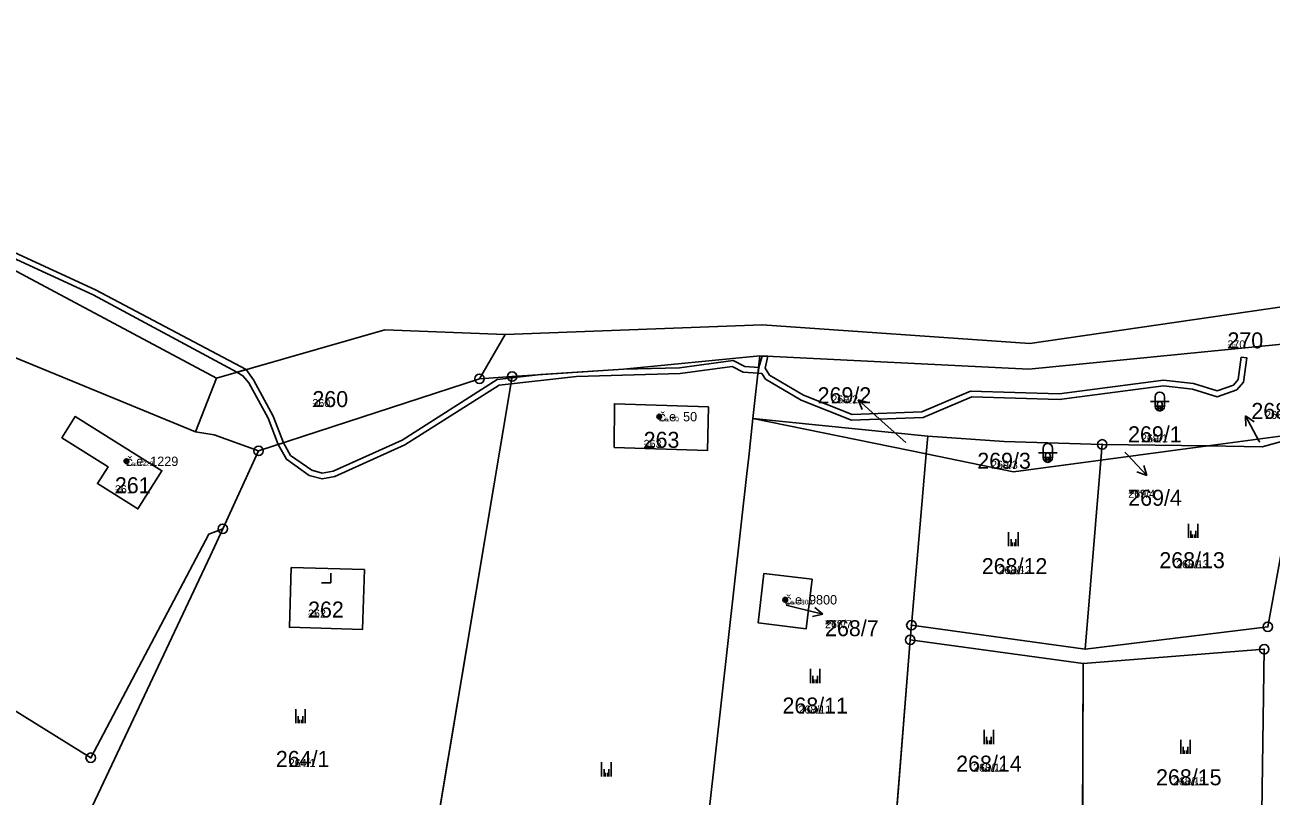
# Model space of a CAD drawing. Extents: x -759873 to -758487, y -975024 to -973516.
# Drawn here: x -758821 to -758688.7, y -974723.5 to -974641.6 of the extents above; entities that cross this region are included whole.
import ezdxf

# ---------------------------------------------------------------- set-up
doc = ezdxf.new("R2010")
doc.units = 0
for name, color, linetype in [('KAT_02_hranice parcel', 7, 'Continuous'), ('KAT_03_1000_st čísla parcelní', 7, 'Continuous'), ('KAT_03_1000_čísla parcelní', 7, 'Continuous'), ('KAT_03_1000_čísla popisná', 7, 'Continuous'), ('KAT_03_250_st čísla parcelní', 7, 'Continuous'), ('KAT_03_250_čísla parcelní', 7, 'Continuous'), ('KAT_03_250_čísla popisná', 7, 'Continuous'), ('KAT_03_500_st čísla parcelní', 7, 'Continuous'), ('KAT_03_500_čísla parcelní', 7, 'Continuous'), ('KAT_03_500_čísla popisná', 7, 'Continuous'), ('KAT_05_1000_značky kultur', 7, 'Continuous'), ('KAT_05_250_značky kultur', 7, 'Continuous'), ('KAT_05_500_značky kultur', 7, 'Continuous'), ('KAT_07_1000_značky budov', 7, 'Continuous'), ('KAT_07_250_značky budov', 7, 'Continuous'), ('KAT_07_500_značky budov', 7, 'Continuous'), ('KAT_10_věcná břemena', 7, 'Continuous'), ('KAT_11_značky bodu BP', 7, 'Continuous'), ('KAT_12_pomocná šipka', 7, 'Continuous'), ('KAT_14_plocha_budovy', 7, 'Continuous'), ('KAT_14_plocha_pozemek', 7, 'Continuous')]:
    doc.layers.add(name, color=color, linetype=linetype)

msp = doc.modelspace()

# ---------------------------------------------------------------- linework, layer by layer
at = {"layer": 'KAT_02_hranice parcel'}
for p, q in [((-758772.79, -974679.2), (-758770.04, -974674.49)), ((-758743, -974676.78), (-758743.77, -974683.44)), ((-758802.92, -974684.85), (-758800.69, -974679.14)), ((-758796.23, -974686.87), (-758772.79, -974679.2)), ((-758780.91, -974748.2), (-758769.32, -974678.97)), ((-758772.79, -974679.2), (-758769.32, -974678.97)), ((-758743.77, -974683.44), (-758725.19, -974685.31)), ((-758743.77, -974683.44), (-758725.35, -974687.19)), ((-758695.47, -974686.34), (-758686.97, -974685.21)), ((-758725.35, -974687.19), (-758725.19, -974685.31)), ((-758706.8, -974687.84), (-758706.66, -974686.17)), ((-758706.8, -974687.84), (-758695.47, -974686.34)), ((-758706.66, -974686.17), (-758695.47, -974686.34)), ((-758800.04, -974695.13), (-758796.23, -974686.87)), ((-758726.93, -974705.38), (-758725.35, -974687.19)), ((-758708.48, -974707.93), (-758706.8, -974687.84)), ((-758726.93, -974705.38), (-758727.05, -974706.93)), ((-758708.48, -974707.93), (-758726.93, -974705.38)), ((-758728.61, -974726.68), (-758727.05, -974706.93)), ((-758727.05, -974706.93), (-758708.68, -974709.44)), ((-758708.76, -974729.74), (-758708.68, -974709.44))]:
    msp.add_line(p, q, dxfattribs=at)
for points in [[(-758800.69, -974679.14), (-758829.75, -974663.64), (-758830.87, -974663.12)], [(-758627.78, -974672.1), (-758635.66, -974671.11), (-758664.13, -974667.52), (-758681.5, -974670.69), (-758714.34, -974675.47), (-758742.76, -974673.48), (-758770.04, -974674.49)], [(-758846.61, -974699.26), (-758838.64, -974683.01), (-758833.34, -974672.35), (-758802.92, -974684.85)], [(-758770.04, -974674.49), (-758782.83, -974674), (-758800.69, -974679.14)], [(-758743, -974676.78), (-758714.44, -974678.18), (-758679.66, -974674.74)], [(-758769.32, -974678.97), (-758757.5, -974678.19), (-758743, -974676.78)], [(-758748.48, -974682.19), (-758758.46, -974681.86), (-758758.48, -974686.49), (-758748.56, -974686.81), (-758748.48, -974682.19)], [(-758815.7, -974683.2), (-758806.5, -974688.97), (-758809.05, -974693.03), (-758813.35, -974690.34), (-758812.22, -974688.54), (-758817.12, -974685.46), (-758815.7, -974683.2)], [(-758743.77, -974683.44), (-758744.2, -974687.51), (-758744.4, -974689.28), (-758748.41, -974725.03)], [(-758796.23, -974686.87), (-758800.96, -974685.16), (-758802.92, -974684.85)], [(-758725.19, -974685.31), (-758717.09, -974685.85), (-758706.66, -974686.17)], [(-758695.47, -974686.34), (-758689.7, -974686.42), (-758687.25, -974685.75)], [(-758725.35, -974687.19), (-758716.08, -974689.07), (-758706.8, -974687.84)], [(-758686.52, -974691.5), (-758689.09, -974705.54), (-758708.48, -974707.93)], [(-758846.61, -974699.26), (-758814.06, -974719.44), (-758801.52, -974695.69), (-758800.04, -974695.13)], [(-758820.96, -974734.87), (-758818.51, -974734.4), (-758801.37, -974698.03), (-758800.04, -974695.13)], [(-758792.77, -974699.23), (-758792.96, -974705.59), (-758785.19, -974705.82), (-758785, -974699.46), (-758792.77, -974699.23)], [(-758742.58, -974699.88), (-758743.21, -974705.11), (-758738.1, -974705.76), (-758737.47, -974700.5), (-758742.58, -974699.88)], [(-758708.68, -974709.44), (-758689.46, -974707.93), (-758689.78, -974730.19)]]:
    msp.add_lwpolyline(points, dxfattribs=at)
at = {"layer": 'KAT_03_1000_čísla popisná'}
for centre in [(-758753.69, -974683.23), (-758810.26, -974687.97), (-758740.32, -974702.67)]:
    msp.add_circle(centre, 0.25, dxfattribs=at)
at = {"layer": 'KAT_03_250_čísla popisná'}
for centre in [(-758753.69, -974683.23), (-758810.26, -974687.97), (-758740.32, -974702.67)]:
    msp.add_circle(centre, 0.0625, dxfattribs=at)
at = {"layer": 'KAT_03_500_čísla popisná'}
for centre in [(-758753.69, -974683.23), (-758810.26, -974687.97), (-758740.32, -974702.67)]:
    msp.add_circle(centre, 0.125, dxfattribs=at)
at = {"layer": 'KAT_05_1000_značky kultur'}
for p, q in [((-758701.05, -974681.12), (-758701.05, -974682.12)), ((-758700.05, -974682.12), (-758700.05, -974681.12)), ((-758701.55, -974681.62), (-758699.55, -974681.62)), ((-758713.44, -974687.08), (-758711.44, -974687.08)), ((-758712.94, -974686.58), (-758712.94, -974687.58)), ((-758711.94, -974687.58), (-758711.94, -974686.58)), ((-758716.6, -974696.98), (-758716.6, -974695.48)), ((-758715.6, -974696.98), (-758715.6, -974695.48)), ((-758697.5, -974696.11), (-758697.5, -974694.61)), ((-758696.5, -974696.11), (-758696.5, -974694.61)), ((-758789.57, -974700.86), (-758788.57, -974700.86)), ((-758788.57, -974700.86), (-758788.57, -974699.86)), ((-758737.65, -974711.51), (-758737.65, -974710.01)), ((-758736.65, -974711.51), (-758736.65, -974710.01)), ((-758792.29, -974715.79), (-758792.29, -974714.29)), ((-758791.29, -974715.79), (-758791.29, -974714.29)), ((-758719.21, -974717.99), (-758719.21, -974716.49)), ((-758718.21, -974717.99), (-758718.21, -974716.49)), ((-758698.33, -974719.03), (-758698.33, -974717.53)), ((-758697.33, -974719.03), (-758697.33, -974717.53)), ((-758759.81, -974721.42), (-758759.81, -974719.92)), ((-758758.81, -974721.42), (-758758.81, -974719.92))]:
    msp.add_line(p, q, dxfattribs=at)
for centre, start, end in [((-758700.55, -974681.12), 0, 180), ((-758700.55, -974682.12), 180, 359.9879), ((-758712.44, -974686.58), 0, 180), ((-758712.44, -974687.58), 180, 359.9879)]:
    msp.add_arc(centre, 0.5, start, end, dxfattribs=at)
at = {"layer": 'KAT_05_250_značky kultur'}
for p, q in [((-758700.8, -974682.37), (-758700.3, -974682.37)), ((-758700.68, -974682.25), (-758700.68, -974682.5)), ((-758700.42, -974682.5), (-758700.42, -974682.25)), ((-758712.69, -974687.83), (-758712.19, -974687.83)), ((-758712.57, -974687.71), (-758712.57, -974687.96)), ((-758712.31, -974687.96), (-758712.31, -974687.71)), ((-758697.12, -974696.11), (-758697.12, -974695.73)), ((-758696.87, -974696.11), (-758696.87, -974695.73)), ((-758716.22, -974696.98), (-758716.22, -974696.6)), ((-758715.97, -974696.98), (-758715.97, -974696.6)), ((-758788.82, -974700.86), (-758788.57, -974700.86)), ((-758788.57, -974700.86), (-758788.57, -974700.61)), ((-758737.27, -974711.51), (-758737.27, -974711.14)), ((-758737.02, -974711.51), (-758737.02, -974711.14)), ((-758791.91, -974715.79), (-758791.91, -974715.42)), ((-758791.66, -974715.79), (-758791.66, -974715.42)), ((-758718.83, -974717.99), (-758718.83, -974717.61)), ((-758718.58, -974717.99), (-758718.58, -974717.61)), ((-758697.95, -974719.03), (-758697.95, -974718.66)), ((-758697.7, -974719.03), (-758697.7, -974718.66)), ((-758759.43, -974721.42), (-758759.43, -974721.05)), ((-758759.18, -974721.42), (-758759.18, -974721.05))]:
    msp.add_line(p, q, dxfattribs=at)
for centre, start, end in [((-758700.55, -974682.25), 0, 180), ((-758700.55, -974682.5), 180, 359.9879), ((-758712.44, -974687.71), 0, 180), ((-758712.44, -974687.96), 180, 359.9879)]:
    msp.add_arc(centre, 0.125, start, end, dxfattribs=at)
at = {"layer": 'KAT_05_500_značky kultur'}
for p, q in [((-758701.05, -974682.12), (-758700.05, -974682.12)), ((-758700.8, -974681.87), (-758700.8, -974682.37)), ((-758700.3, -974682.37), (-758700.3, -974681.87)), ((-758712.94, -974687.58), (-758711.94, -974687.58)), ((-758712.69, -974687.33), (-758712.69, -974687.83)), ((-758712.19, -974687.83), (-758712.19, -974687.33)), ((-758697.25, -974696.11), (-758697.25, -974695.36)), ((-758696.74, -974696.11), (-758696.74, -974695.36)), ((-758716.35, -974696.98), (-758716.35, -974696.23)), ((-758715.84, -974696.98), (-758715.84, -974696.23)), ((-758789.07, -974700.86), (-758788.57, -974700.86)), ((-758788.57, -974700.86), (-758788.57, -974700.36)), ((-758737.4, -974711.51), (-758737.4, -974710.76)), ((-758736.9, -974711.51), (-758736.9, -974710.76)), ((-758792.04, -974715.79), (-758792.04, -974715.04)), ((-758791.54, -974715.79), (-758791.54, -974715.04)), ((-758718.96, -974717.99), (-758718.96, -974717.24)), ((-758718.45, -974717.99), (-758718.45, -974717.24)), ((-758698.08, -974719.03), (-758698.08, -974718.28)), ((-758697.58, -974719.03), (-758697.58, -974718.28)), ((-758759.56, -974721.42), (-758759.56, -974720.67)), ((-758759.06, -974721.42), (-758759.06, -974720.67))]:
    msp.add_line(p, q, dxfattribs=at)
for centre, start, end in [((-758700.55, -974681.87), 0, 180), ((-758700.55, -974682.37), 180, 359.9879), ((-758712.44, -974687.33), 0, 180), ((-758712.44, -974687.83), 180, 359.9879)]:
    msp.add_arc(centre, 0.25, start, end, dxfattribs=at)
at = {"layer": 'KAT_07_1000_značky budov'}
for centre in [(-758753.7, -974683.23), (-758810.27, -974687.97), (-758740.33, -974702.67)]:
    msp.add_circle(centre, 0.175, dxfattribs=at)
at = {"layer": 'KAT_07_250_značky budov'}
for centre in [(-758753.69, -974683.23), (-758810.26, -974687.97), (-758740.32, -974702.67)]:
    msp.add_circle(centre, 0.0437, dxfattribs=at)
at = {"layer": 'KAT_07_500_značky budov'}
for centre in [(-758753.69, -974683.23), (-758810.26, -974687.97), (-758740.32, -974702.67)]:
    msp.add_circle(centre, 0.0875, dxfattribs=at)
at = {"layer": 'KAT_10_věcná břemena'}
for points in [[(-758863.87, -974647.67), (-758863.33, -974647.93), (-758851.2, -974653.17), (-758831.96, -974661.95), (-758813.8, -974670.31), (-758798.54, -974678.52), (-758797.54, -974678.23), (-758813.54, -974669.77), (-758831.72, -974661.41), (-758850.96, -974652.63), (-758863.11, -974647.4), (-758862.12, -974644.3), (-758862.83, -974644.55), (-758863.76, -974647.45)], [(-758794.17, -974686.19), (-758793.27, -974687.76), (-758790.85, -974689.47), (-758789.5, -974689.84), (-758788.13, -974689.59), (-758780.71, -974686.23), (-758770.7, -974679.87), (-758762.49, -974678.95), (-758751.49, -974678.63), (-758745.95, -974677.89), (-758744.8, -974678.5), (-758743.21, -974678.62), (-758743.14, -974678.02), (-758744.62, -974677.92), (-758745.83, -974677.27), (-758751.53, -974678.03), (-758757.5, -974678.19), (-758766.26, -974678.77), (-758770.9, -974679.29), (-758780.99, -974685.71), (-758788.31, -974689.01), (-758789.48, -974689.22), (-758790.59, -974688.91), (-758792.83, -974687.34), (-758793.6, -974686.01)], [(-758743.14, -974678.02), (-758743.21, -974678.62), (-758742.8, -974678.65), (-758742.4, -974679.25), (-758738.64, -974681.47), (-758733.3, -974683.59), (-758725.68, -974683.33), (-758720.52, -974681.11), (-758711.23, -974681.42), (-758700.16, -974679.97), (-758697.09, -974680.31), (-758694.45, -974681.14), (-758692.38, -974680.37), (-758691.68, -974679.56), (-758691.31, -974676.99), (-758691.9, -974676.9), (-758692.24, -974679.3), (-758692.74, -974679.87), (-758694.47, -974680.5), (-758696.97, -974679.71), (-758700.16, -974679.37), (-758711.25, -974680.82), (-758720.64, -974680.51), (-758725.82, -974682.73), (-758733.2, -974682.99), (-758738.38, -974680.93), (-758741.98, -974678.81), (-758742.45, -974678.09), (-758742.18, -974676.82), (-758742.78, -974676.79)], [(-758797.54, -974678.23), (-758798.54, -974678.52), (-758797.89, -974678.88), (-758797.27, -974679.65), (-758795.21, -974683.4), (-758794.17, -974686.19), (-758793.6, -974686.01), (-758794.67, -974683.16), (-758796.77, -974679.31)]]:
    msp.add_lwpolyline(points, close=True, dxfattribs=at)
at = {"layer": 'KAT_11_značky bodu BP'}
for centre, radius in [((-758769.32, -974678.97), 0.5), ((-758772.79, -974679.2), 0.5), ((-758772.79, -974679.2), 0.0303), ((-758769.32, -974678.97), 0.0303), ((-758796.23, -974686.87), 0.5), ((-758706.66, -974686.17), 0.5), ((-758706.66, -974686.17), 0.0303), ((-758796.23, -974686.87), 0.0303), ((-758800.04, -974695.13), 0.5), ((-758800.04, -974695.13), 0.0303), ((-758726.93, -974705.38), 0.5), ((-758689.09, -974705.54), 0.5), ((-758726.93, -974705.38), 0.0303), ((-758689.09, -974705.54), 0.0303), ((-758727.05, -974706.93), 0.5), ((-758727.05, -974706.93), 0.0303), ((-758689.46, -974707.93), 0.5), ((-758689.46, -974707.93), 0.0303), ((-758814.06, -974719.44), 0.5), ((-758814.06, -974719.44), 0.0303)]:
    msp.add_circle(centre, radius, dxfattribs=at)
at = {"layer": 'KAT_12_pomocná šipka'}
for p, q in [((-758730.34, -974683.45), (-758732.57, -974681.44)), ((-758732.57, -974681.44), (-758731.49, -974681.74)), ((-758732.57, -974681.44), (-758732.16, -974682.48)), ((-758727.51, -974685.96), (-758730.34, -974683.45)), ((-758690.03, -974685.78), (-758691.44, -974683.13)), ((-758691.44, -974683.13), (-758690.53, -974683.78)), ((-758691.44, -974683.13), (-758691.41, -974684.25)), ((-758689.94, -974685.95), (-758690.03, -974685.78)), ((-758704.26, -974687), (-758703.99, -974687.28)), ((-758703.99, -974687.28), (-758701.94, -974689.47)), ((-758701.94, -974689.47), (-758702.99, -974689.08)), ((-758701.94, -974689.47), (-758702.26, -974688.4)), ((-758740.21, -974703.24), (-758739.23, -974703.48)), ((-758739.23, -974703.48), (-758736.32, -974704.21)), ((-758736.32, -974704.21), (-758737.17, -974703.48)), ((-758736.32, -974704.21), (-758737.41, -974704.45))]:
    msp.add_line(p, q, dxfattribs=at)
at = {"layer": 'KAT_14_plocha_budovy'}
for points in [[(-758758.48, -974686.49), (-758748.56, -974686.81), (-758748.48, -974682.19), (-758758.46, -974681.86)], [(-758817.12, -974685.46), (-758812.22, -974688.54), (-758813.35, -974690.34), (-758809.05, -974693.03), (-758806.5, -974688.97), (-758815.7, -974683.2)], [(-758743.21, -974705.11), (-758738.1, -974705.76), (-758737.47, -974700.5), (-758742.58, -974699.88)]]:
    msp.add_lwpolyline(points, close=True, dxfattribs=at)
at = {"layer": 'KAT_14_plocha_pozemek'}
for points in [[(-758829.75, -974663.64), (-758800.69, -974679.14), (-758782.83, -974674), (-758770.04, -974674.49), (-758742.76, -974673.48), (-758714.34, -974675.47), (-758681.5, -974670.69), (-758664.13, -974667.52), (-758635.66, -974671.11), (-758627.78, -974672.1), (-758618.81, -974624.26), (-758621.91, -974623.53), (-758624.96, -974622.82), (-758670.31, -974612.18), (-758699.89, -974599.55), (-758726.38, -974585.65), (-758760.58, -974546.71), (-758797.73, -974511.01)], [(-758686.52, -974691.5), (-758689.09, -974705.54), (-758708.48, -974707.93), (-758726.93, -974705.38), (-758727.05, -974706.93), (-758708.68, -974709.44), (-758689.46, -974707.93), (-758689.78, -974730.19)]]:
    msp.add_lwpolyline(points, dxfattribs=at)
for points in [[(-758830.87, -974663.12), (-758834.94, -974670.75), (-758841.44, -974684.62), (-758853.59, -974681.81), (-758863.06, -974680.54), (-758877.35, -974674.93), (-758892.08, -974697.79), (-758892.74, -974704.7), (-758858.23, -974722.43), (-758855, -974716.35), (-758846.61, -974699.26), (-758838.64, -974683.01), (-758833.34, -974672.35), (-758802.92, -974684.85), (-758800.69, -974679.14), (-758829.75, -974663.64)], [(-758757.5, -974678.19), (-758743, -974676.78), (-758714.44, -974678.18), (-758679.66, -974674.74), (-758664.4, -974670.24), (-758628.19, -974674.27), (-758627.78, -974672.1), (-758635.66, -974671.11), (-758664.13, -974667.52), (-758681.5, -974670.69), (-758714.34, -974675.47), (-758742.76, -974673.48), (-758770.04, -974674.49), (-758772.79, -974679.2), (-758769.32, -974678.97)], [(-758796.23, -974686.87), (-758800.96, -974685.16), (-758802.92, -974684.85), (-758833.34, -974672.35), (-758838.64, -974683.01), (-758846.61, -974699.26), (-758814.06, -974719.44), (-758801.52, -974695.69), (-758800.04, -974695.13)], [(-758772.79, -974679.2), (-758770.04, -974674.49), (-758782.83, -974674), (-758800.69, -974679.14), (-758802.92, -974684.85), (-758800.96, -974685.16), (-758796.23, -974686.87)], [(-758743, -974676.78), (-758743.77, -974683.44), (-758725.19, -974685.31), (-758717.09, -974685.85), (-758706.66, -974686.17), (-758695.47, -974686.34), (-758686.97, -974685.21), (-758685.99, -974685.08), (-758681.69, -974686.2), (-758679.66, -974674.74), (-758714.44, -974678.18)], [(-758743, -974676.78), (-758757.5, -974678.19), (-758769.32, -974678.97), (-758780.91, -974748.2), (-758773.62, -974749.22), (-758756.23, -974751.65), (-758752, -974752.2), (-758751.31, -974750.65), (-758750.88, -974746.89), (-758750.62, -974744.56), (-758749.39, -974733.79), (-758748.41, -974725.03), (-758744.4, -974689.28), (-758744.2, -974687.51), (-758743.77, -974683.44)], [(-758780.91, -974748.2), (-758769.32, -974678.97), (-758772.79, -974679.2), (-758796.23, -974686.87), (-758800.04, -974695.13), (-758801.37, -974698.03), (-758818.51, -974734.4), (-758820.96, -974734.87), (-758816.27, -974737.96), (-758791.45, -974746.72), (-758787.33, -974747.3)], [(-758748.48, -974682.19), (-758758.46, -974681.86), (-758758.48, -974686.49), (-758748.56, -974686.81)], [(-758748.48, -974682.19), (-758748.56, -974686.81), (-758758.48, -974686.49), (-758758.46, -974681.86)], [(-758815.7, -974683.2), (-758806.5, -974688.97), (-758809.05, -974693.03), (-758813.35, -974690.34), (-758812.22, -974688.54), (-758817.12, -974685.46)], [(-758815.7, -974683.2), (-758817.12, -974685.46), (-758812.22, -974688.54), (-758813.35, -974690.34), (-758809.05, -974693.03), (-758806.5, -974688.97)], [(-758744.4, -974689.28), (-758748.41, -974725.03), (-758728.61, -974726.68), (-758727.05, -974706.93), (-758726.93, -974705.38), (-758725.35, -974687.19), (-758743.77, -974683.44), (-758744.2, -974687.51)], [(-758725.35, -974687.19), (-758725.19, -974685.31), (-758743.77, -974683.44)], [(-758687.25, -974685.75), (-758686.97, -974685.21), (-758695.47, -974686.34), (-758689.7, -974686.42)], [(-758706.8, -974687.84), (-758706.66, -974686.17), (-758717.09, -974685.85), (-758725.19, -974685.31), (-758725.35, -974687.19), (-758716.08, -974689.07)], [(-758695.47, -974686.34), (-758706.8, -974687.84), (-758708.48, -974707.93), (-758689.09, -974705.54), (-758686.52, -974691.5), (-758687.25, -974685.75), (-758689.7, -974686.42)], [(-758695.47, -974686.34), (-758706.66, -974686.17), (-758706.8, -974687.84)], [(-758708.48, -974707.93), (-758706.8, -974687.84), (-758716.08, -974689.07), (-758725.35, -974687.19), (-758726.93, -974705.38)], [(-758800.04, -974695.13), (-758801.52, -974695.69), (-758814.06, -974719.44), (-758846.61, -974699.26), (-758855, -974716.35), (-758858.23, -974722.43), (-758831.39, -974738.61), (-758825.18, -974736.38), (-758820.96, -974734.87), (-758818.51, -974734.4), (-758801.37, -974698.03)], [(-758792.77, -974699.23), (-758792.96, -974705.59), (-758785.19, -974705.82), (-758785, -974699.46)], [(-758792.77, -974699.23), (-758785, -974699.46), (-758785.19, -974705.82), (-758792.96, -974705.59)], [(-758742.58, -974699.88), (-758743.21, -974705.11), (-758738.1, -974705.76), (-758737.47, -974700.5)], [(-758742.58, -974699.88), (-758737.47, -974700.5), (-758738.1, -974705.76), (-758743.21, -974705.11)], [(-758728.68, -974727.47), (-758708.76, -974729.74), (-758708.68, -974709.44), (-758727.05, -974706.93), (-758728.61, -974726.68)], [(-758689.78, -974730.19), (-758689.46, -974707.93), (-758708.68, -974709.44), (-758708.76, -974729.74)]]:
    msp.add_lwpolyline(points, close=True, dxfattribs=at)

# ---------------------------------------------------------------- texts
at = {"layer": 'KAT_03_1000_st čísla parcelní'}
for s, p in [('263', (-758755.35, -974686.54)), ('261', (-758811.49, -974691.36)), ('262', (-758790.98, -974704.56)), ('268/7', (-758736.09, -974706.54))]:
    msp.add_text(s, height=1.7, dxfattribs=at).set_placement(p)
at = {"layer": 'KAT_03_1000_čísla parcelní'}
for s, p in [('270', (-758693.37, -974675.98)), ('260', (-758790.52, -974682.21)), ('269/2', (-758736.88, -974681.81)), ('268/8', (-758690.83, -974683.47)), ('269/1', (-758703.92, -974685.95)), ('269/3', (-758719.93, -974688.76)), ('269/4', (-758703.9, -974692.69)), ('268/12', (-758719.45, -974699.95)), ('268/13', (-758700.6, -974699.32)), ('268/11', (-758740.61, -974714.75)), ('264/1', (-758794.4, -974720.42)), ('268/14', (-758722.17, -974720.92)), ('268/15', (-758700.95, -974722.37))]:
    msp.add_text(s, height=1.7, dxfattribs=at).set_placement(p)
at = {"layer": 'KAT_03_1000_čísla popisná'}
for s, p in [('č.e. 50', (-758753.69, -974683.73)), ('č.e. 1229', (-758810.26, -974688.47)), ('č.e. 9800', (-758740.32, -974703.17))]:
    msp.add_text(s, height=1, dxfattribs=at).set_placement(p)
at = {"layer": 'KAT_03_250_st čísla parcelní'}
for s, p in [('263', (-758755.35, -974686.54)), ('261', (-758811.49, -974691.36)), ('262', (-758790.98, -974704.56)), ('268/7', (-758736.09, -974705.27))]:
    msp.add_text(s, height=0.425, dxfattribs=at).set_placement(p)
at = {"layer": 'KAT_03_250_čísla parcelní'}
for s, p in [('270', (-758693.37, -974675.98)), ('260', (-758790.52, -974682.21)), ('269/2', (-758734.7, -974681.81)), ('269/1', (-758701.86, -974685.95)), ('269/3', (-758717.75, -974688.76)), ('269/4', (-758703.9, -974691.42)), ('268/12', (-758716.78, -974699.95)), ('268/13', (-758697.92, -974699.32)), ('268/11', (-758738.06, -974714.75)), ('264/1', (-758792.34, -974720.42)), ('268/14', (-758719.49, -974720.92)), ('268/15', (-758698.27, -974722.37))]:
    msp.add_text(s, height=0.425, dxfattribs=at).set_placement(p)
at = {"layer": 'KAT_03_250_čísla popisná'}
for s, p in [('č.e. 50', (-758753.69, -974683.73)), ('č.e. 1229', (-758810.26, -974688.47)), ('č.e. 9800', (-758740.32, -974703.17))]:
    msp.add_text(s, height=0.25, dxfattribs=at).set_placement(p)
at = {"layer": 'KAT_03_500_st čísla parcelní'}
for s, p in [('263', (-758755.35, -974686.54)), ('261', (-758811.49, -974691.36)), ('262', (-758790.98, -974704.56)), ('268/7', (-758736.09, -974705.69))]:
    msp.add_text(s, height=0.85, dxfattribs=at).set_placement(p)
at = {"layer": 'KAT_03_500_čísla parcelní'}
for s, p in [('270', (-758693.37, -974675.98)), ('269/2', (-758735.43, -974681.81)), ('260', (-758790.52, -974682.21)), ('268/8', (-758689.37, -974683.47)), ('269/1', (-758702.55, -974685.95)), ('269/3', (-758718.47, -974688.76)), ('269/4', (-758703.9, -974691.84)), ('268/13', (-758698.82, -974699.32)), ('268/12', (-758717.67, -974699.95)), ('268/11', (-758738.91, -974714.75)), ('264/1', (-758793.03, -974720.42)), ('268/14', (-758720.38, -974720.92)), ('268/15', (-758699.16, -974722.37))]:
    msp.add_text(s, height=0.85, dxfattribs=at).set_placement(p)
at = {"layer": 'KAT_03_500_čísla popisná'}
for s, p in [('č.e. 50', (-758753.69, -974683.73)), ('č.e. 1229', (-758810.26, -974688.47)), ('č.e. 9800', (-758740.32, -974703.17))]:
    msp.add_text(s, height=0.5, dxfattribs=at).set_placement(p)

doc.saveas('drawing.dxf')
